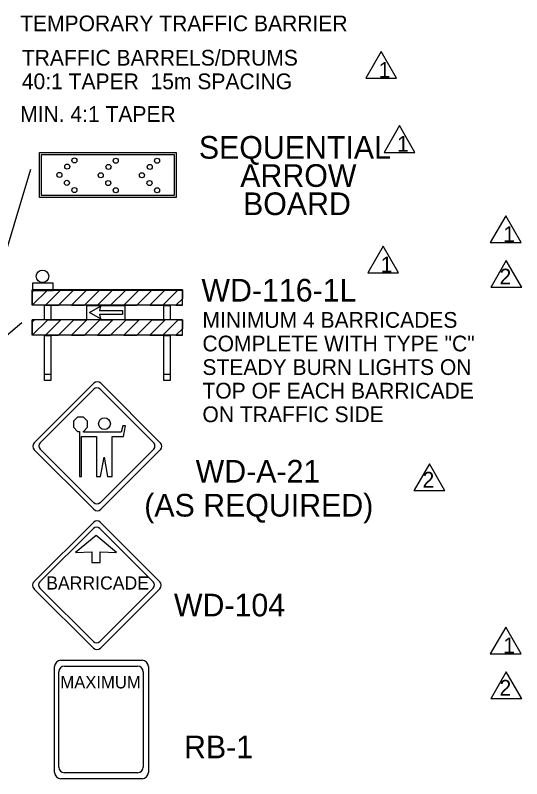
# Model space of a CAD drawing. Extents: x 2179 to 2395, y 134 to 413.
# Drawn here: x 2238.8 to 2285.4, y 256.2 to 326.7 of the extents above; entities that cross this region are included whole.
import ezdxf

# ---------------------------------------------------------------- set-up
doc = ezdxf.new("R2010")
doc.units = 0
for name, color, linetype in [('Level 1', 7, 'Continuous'), ('Level 10', 7, 'Continuous'), ('Level 44', 7, 'Continuous'), ('Level 5', 7, 'Continuous'), ('Level 60', 7, 'Continuous')]:
    doc.layers.add(name, color=color, linetype=linetype)

# ---------------------------------------------------------------- blocks, each defined once
blk = doc.blocks.new('REV1')
at = {"layer": 'Level 1'}
blk.add_lwpolyline([(0.114, 1.689), (-1.305, -0.781), (1.533, -0.781)], close=True, dxfattribs=at)
blk.add_text('1', height=1.448, rotation=360, dxfattribs=at).set_placement((-0.113, -0.724))

msp = doc.modelspace()

# ---------------------------------------------------------------- linework, layer by layer
at = {"layer": 'Level 1'}
for p, q in [((2244.503, 289.596), (2244.12, 289.213)), ((2245.046, 289.596), (2244.503, 289.596)), ((2245.429, 289.213), (2245.046, 289.596)), ((2244.12, 289.213), (2244.12, 288.67)), ((2245.429, 288.67), (2245.429, 289.213)), ((2248.662, 288.799), (2248.522, 288.216)), ((2248.906, 288.799), (2248.662, 288.799)), ((2248.747, 287.825), (2248.906, 288.799)), ((2244.12, 288.67), (2244.503, 288.287)), ((2244.503, 288.287), (2244.677, 288.287)), ((2244.677, 288.287), (2244.677, 284.133)), ((2245.046, 288.287), (2245.429, 288.67)), ((2245.046, 288.216), (2245.046, 288.287)), ((2248.522, 288.216), (2245.046, 288.216)), ((2244.867, 284.133), (2244.867, 287.825)), ((2244.867, 287.825), (2246.25, 287.825)), ((2246.25, 287.825), (2246.25, 284.133)), ((2247.699, 284.133), (2247.699, 287.825)), ((2247.699, 287.825), (2248.747, 287.825)), ((2246.617, 284.133), (2246.944, 285.902)), ((2246.944, 285.902), (2247.253, 284.133)), ((2244.677, 284.133), (2244.867, 284.133)), ((2246.25, 284.133), (2246.617, 284.133)), ((2247.253, 284.133), (2247.699, 284.133))]:
    msp.add_line(p, q, dxfattribs=at)
msp.add_circle((2246.979, 288.994), 0.544, dxfattribs=at)
at = {"layer": 'Level 10'}
for p, q in [((2235.526, 296.914), (2240.183, 312.477)), ((2232.288, 292.347), (2239.364, 298.329))]:
    msp.add_line(p, q, dxfattribs=at)
msp.add_lwpolyline([(2240.358, 301.278), (2242.264, 301.278), (2242.264, 301.97), (2240.358, 301.97)], close=True, dxfattribs=at)
msp.add_circle((2241.266, 302.586), 0.576, dxfattribs=at)
at = {"layer": 'Level 44'}
for p, q in [((2240.998, 309.868), (2240.998, 313.998)), ((2240.998, 313.998), (2253.579, 313.998)), ((2241.186, 310.056), (2241.186, 313.812)), ((2241.186, 313.812), (2253.391, 313.812)), ((2253.391, 313.812), (2253.391, 310.056)), ((2253.579, 313.998), (2253.579, 309.868)), ((2253.579, 309.868), (2240.998, 309.868)), ((2253.391, 310.056), (2241.186, 310.056)), ((2245.995, 292.725), (2240.501, 287.239)), ((2252.129, 287.239), (2246.644, 292.725)), ((2241.051, 287.235), (2245.995, 292.172)), ((2246.579, 292.172), (2251.517, 287.235)), ((2245.995, 281.708), (2241.051, 286.648)), ((2251.517, 286.648), (2246.579, 281.708)), ((2240.501, 286.588), (2245.995, 281.097)), ((2240.506, 286.588), (2240.501, 286.588)), ((2246.644, 281.097), (2252.129, 286.588)), ((2245.961, 279.89), (2240.483, 274.421)), ((2252.077, 274.421), (2246.608, 279.89)), ((2241.032, 274.416), (2245.961, 279.339)), ((2246.544, 279.339), (2251.467, 274.416)), ((2246.203, 278.693), (2244.32, 277.106)), ((2248.084, 277.106), (2246.203, 278.693)), ((2244.32, 277.106), (2245.825, 277.187)), ((2245.825, 277.187), (2245.825, 276.183)), ((2246.579, 276.183), (2246.579, 277.187)), ((2246.579, 277.187), (2248.084, 277.106)), ((2245.825, 276.183), (2246.575, 276.183)), ((2240.483, 273.771), (2245.961, 268.296)), ((2240.488, 273.771), (2240.483, 273.771)), ((2245.961, 268.905), (2241.032, 273.832)), ((2251.467, 273.832), (2246.544, 268.905)), ((2246.608, 268.296), (2252.077, 273.771)), ((2242.964, 267.174), (2250.46, 267.174)), ((2242.386, 256.825), (2242.386, 266.595)), ((2243.292, 266.635), (2250.038, 266.635)), ((2251.04, 266.595), (2251.04, 256.825)), ((2242.772, 257.319), (2242.772, 266.114)), ((2250.56, 266.114), (2250.56, 257.319)), ((2242.772, 257.318), (2242.772, 257.319)), ((2242.386, 256.822), (2242.386, 256.825)), ((2250.038, 256.798), (2243.292, 256.798)), ((2250.46, 256.244), (2242.964, 256.244))]:
    msp.add_line(p, q, dxfattribs=at)
for centre in [(2244.214, 313.275), (2248.019, 313.246), (2251.825, 313.246), (2243.549, 312.703), (2247.354, 312.675), (2251.159, 312.675), (2242.827, 311.934), (2246.632, 311.906), (2250.438, 311.906), (2243.521, 311.213), (2247.326, 311.184), (2251.131, 311.184), (2244.214, 310.547), (2248.019, 310.519), (2251.825, 310.519)]:
    msp.add_circle(centre, 0.234, dxfattribs=at)
for centre, radius, start, end in [((2246.318, 292.402), 0.459, 45, 135), ((2246.286, 291.881), 0.413, 45, 135), ((2240.83, 286.913), 0.459, 135, 224.99999), ((2241.346, 286.941), 0.413, 135, 224.99999), ((2251.226, 286.941), 0.413, 315, 45), ((2251.807, 286.913), 0.459, 315, 45), ((2246.286, 282.002), 0.413, 225, 315), ((2246.318, 281.425), 0.459, 225, 315), ((2246.284, 279.568), 0.458, 45, 135), ((2246.251, 279.049), 0.412, 45, 135), ((2240.811, 274.096), 0.458, 135, 224.99999), ((2241.326, 274.124), 0.412, 135, 224.99999), ((2251.177, 274.124), 0.412, 315, 45), ((2251.756, 274.096), 0.458, 315, 45), ((2246.251, 269.198), 0.412, 225, 315), ((2246.284, 268.623), 0.458, 225, 315), ((2242.965, 266.595), 0.578, 90, 179.99999), ((2250.46, 266.595), 0.578, 359.99999, 89.99999), ((2243.293, 266.113), 0.52, 90, 179.99999), ((2250.038, 266.113), 0.52, 359.99999, 89.99999), ((2243.293, 257.318), 0.52, 180, 269.99999), ((2250.038, 257.318), 0.52, 270, 359.99999), ((2242.965, 256.823), 0.578, 180, 269.99999), ((2250.46, 256.823), 0.578, 270, 359.99999)]:
    msp.add_arc(centre, radius, start, end, dxfattribs=at)
at = {"layer": 'Level 5'}
for p, q in [((2254.17, 301.334), (2240.328, 301.334)), ((2240.328, 299.915), (2240.328, 301.334)), ((2254.185, 301.306), (2240.343, 301.306)), ((2240.343, 301.306), (2254.185, 301.306)), ((2241.478, 301.306), (2241.761, 301.306)), ((2253.035, 301.334), (2252.752, 301.334)), ((2253.051, 301.306), (2252.767, 301.306)), ((2254.17, 299.915), (2254.17, 301.334)), ((2254.17, 299.915), (2240.328, 299.915)), ((2241.463, 299.888), (2241.463, 299.915)), ((2245.381, 299.901), (2248.869, 299.901)), ((2245.381, 299.901), (2248.869, 299.901)), ((2252.468, 299.888), (2252.468, 299.915)), ((2240.328, 297.151), (2240.328, 298.569)), ((2254.17, 298.569), (2240.328, 298.569)), ((2253.035, 298.569), (2252.752, 298.569)), ((2254.17, 297.151), (2254.17, 298.569)), ((2254.17, 297.151), (2240.328, 297.151)), ((2242.03, 293.534), (2241.463, 293.534)), ((2253.035, 293.534), (2252.468, 293.534))]:
    msp.add_line(p, q, dxfattribs=at)
for points in [[(2240.328, 299.915), (2241.746, 301.334), (2240.543, 301.334), (2240.328, 301.119), (2240.328, 299.915)], [(2242.735, 299.915), (2244.153, 301.334), (2242.949, 301.334), (2241.531, 299.915), (2242.735, 299.915)], [(2245.142, 299.915), (2246.56, 301.334), (2245.356, 301.334), (2243.938, 299.915), (2245.142, 299.915)], [(2247.548, 299.915), (2248.966, 301.334), (2247.763, 301.334), (2246.345, 299.915), (2247.548, 299.915)], [(2251.373, 301.334), (2250.17, 301.334), (2248.752, 299.915), (2249.955, 299.915), (2251.373, 301.334)], [(2253.78, 301.334), (2252.578, 301.334), (2251.159, 299.915), (2252.363, 299.915), (2253.78, 301.334)], [(2254.17, 300.521), (2253.565, 299.915), (2254.17, 299.915), (2254.17, 300.521)], [(2240.328, 297.151), (2241.746, 298.569), (2240.543, 298.569), (2240.328, 298.354), (2240.328, 297.151)], [(2242.735, 297.151), (2244.153, 298.569), (2242.949, 298.569), (2241.531, 297.151), (2242.735, 297.151)], [(2245.142, 297.151), (2246.56, 298.569), (2245.356, 298.569), (2243.938, 297.151), (2245.142, 297.151)], [(2247.548, 297.151), (2248.966, 298.569), (2247.763, 298.569), (2246.345, 297.151), (2247.548, 297.151)], [(2251.373, 298.569), (2250.17, 298.569), (2248.752, 297.151), (2249.955, 297.151), (2251.373, 298.569)], [(2253.78, 298.569), (2252.578, 298.569), (2251.159, 297.151), (2252.363, 297.151), (2253.78, 298.569)], [(2254.17, 297.755), (2253.565, 297.151), (2254.17, 297.151), (2254.17, 297.755)]]:
    msp.add_lwpolyline(points, dxfattribs=at)
for points in [[(2241.746, 301.334), (2242.949, 301.334), (2241.531, 299.915), (2240.328, 299.915)], [(2240.543, 301.334), (2240.328, 301.334), (2240.328, 301.119)], [(2244.153, 301.334), (2245.356, 301.334), (2243.938, 299.915), (2242.735, 299.915)], [(2246.56, 301.334), (2247.763, 301.334), (2246.345, 299.915), (2245.142, 299.915)], [(2248.966, 301.334), (2250.17, 301.334), (2248.752, 299.915), (2247.548, 299.915)], [(2251.373, 301.334), (2252.578, 301.334), (2251.159, 299.915), (2249.955, 299.915)], [(2253.78, 301.334), (2254.17, 301.334), (2254.17, 300.521), (2253.565, 299.915), (2252.363, 299.915)], [(2241.463, 299.888), (2242.03, 299.915), (2242.03, 298.569), (2241.463, 298.569)], [(2248.869, 299.901), (2248.869, 298.569), (2245.356, 298.569), (2245.356, 299.901)], [(2248.642, 299.436), (2248.642, 299.062), (2246.515, 299.062), (2246.629, 298.664), (2245.608, 299.249), (2246.629, 299.833), (2246.515, 299.436)], [(2252.468, 299.888), (2253.035, 299.888), (2253.035, 298.569), (2252.468, 298.569)], [(2240.328, 298.569), (2240.543, 298.569), (2240.328, 298.354)], [(2241.746, 298.569), (2242.949, 298.569), (2241.531, 297.151), (2240.328, 297.151)], [(2244.153, 298.569), (2245.356, 298.569), (2243.938, 297.151), (2242.735, 297.151)], [(2246.56, 298.569), (2247.763, 298.569), (2246.345, 297.151), (2245.142, 297.151)], [(2248.966, 298.569), (2250.17, 298.569), (2248.752, 297.151), (2247.548, 297.151)], [(2251.373, 298.569), (2252.578, 298.569), (2251.159, 297.151), (2249.955, 297.151)], [(2253.78, 298.569), (2254.17, 298.569), (2254.17, 297.755), (2253.565, 297.151), (2252.363, 297.151)], [(2241.463, 297.136), (2242.03, 297.136), (2242.03, 292.966), (2241.463, 292.966)], [(2252.468, 297.136), (2253.035, 297.136), (2253.035, 292.966), (2252.468, 292.966)]]:
    msp.add_lwpolyline(points, close=True, dxfattribs=at)
at = {"layer": 'Level 60'}
for points in [[(2284.028, 304.041), (2282.635, 301.616)], [(2285.422, 301.616), (2284.028, 304.041)], [(2282.635, 301.616), (2282.609, 301.571), (2285.448, 301.571), (2285.422, 301.616)], [(2276.933, 285.301), (2275.54, 282.876)], [(2278.327, 282.876), (2276.933, 285.301)], [(2275.54, 282.876), (2275.514, 282.831), (2278.353, 282.831), (2278.327, 282.876)], [(2284.028, 266.112), (2282.635, 263.687)], [(2285.422, 263.687), (2284.028, 266.112)], [(2282.635, 263.687), (2282.609, 263.642), (2285.448, 263.642), (2285.422, 263.687)]]:
    msp.add_lwpolyline(points, dxfattribs=at)

# ---------------------------------------------------------------- block references
at = {"layer": 'Level 1'}
for p in [(2272.373, 321.633), (2274.066, 314.796), (2283.856, 306.472), (2272.562, 303.675), (2283.856, 268.542)]:
    msp.add_blockref('REV1', p, dxfattribs=at)

# ---------------------------------------------------------------- texts
at = {"layer": 'Level 10'}
for s, height, p in [('TEMPORARY TRAFFIC BARRIER', 1.451, (2239.206, 325.193)), ('TRAFFIC BARRELS/DRUMS', 1.4514, (2239.362, 322.022)), ('40:1 TAPER  15m SPACING', 1.4514, (2239.362, 319.846)), ('MIN. 4:1 TAPER', 1.451, (2239.206, 316.831)), ('WD-116-1L', 2.09, (2255.919, 300.259)), ('MINIMUM 4 BARRICADES', 1.4514, (2256.012, 297.839)), ('COMPLETE WITH TYPE "C" ', 1.4514, (2256.012, 295.663)), ('STEADY BURN LIGHTS ON ', 1.4514, (2256.012, 293.487)), ('TOP OF EACH BARRICADE ', 1.4514, (2256.012, 291.311)), ('ON TRAFFIC SIDE', 1.4514, (2256.012, 289.135)), ('WD-A-21', 2.09, (2255.387, 283.56)), ('(AS REQUIRED)', 2.09001, (2250.647, 280.426)), ('WD-104', 2.09, (2253.385, 271.221)), ('RB-1', 2.09, (2254.316, 258.131))]:
    msp.add_text(s, height=height, dxfattribs=at).set_placement(p)
for s, p in [('SEQUENTIAL', (2255.682, 313.437)), ('ARROW', (2259.5, 310.837)), ('BOARD', (2259.755, 308.236))]:
    msp.add_text(s, height=2.09, rotation=0, dxfattribs=at).set_placement(p)
at = {"layer": 'Level 44'}
for s, height, p in [('BARRICADE', 1.2144, (2241.609, 273.695)), ('MAXIMUM', 1.1467, (2242.914, 264.576))]:
    msp.add_text(s, height=height, rotation=360, dxfattribs=at).set_placement(p)
at = {"layer": 'Level 60'}
for p in [(2283.401, 301.84), (2276.306, 283.1), (2283.401, 263.911)]:
    msp.add_text('2', height=1.448, rotation=360, dxfattribs=at).set_placement(p)

doc.saveas('drawing.dxf')
